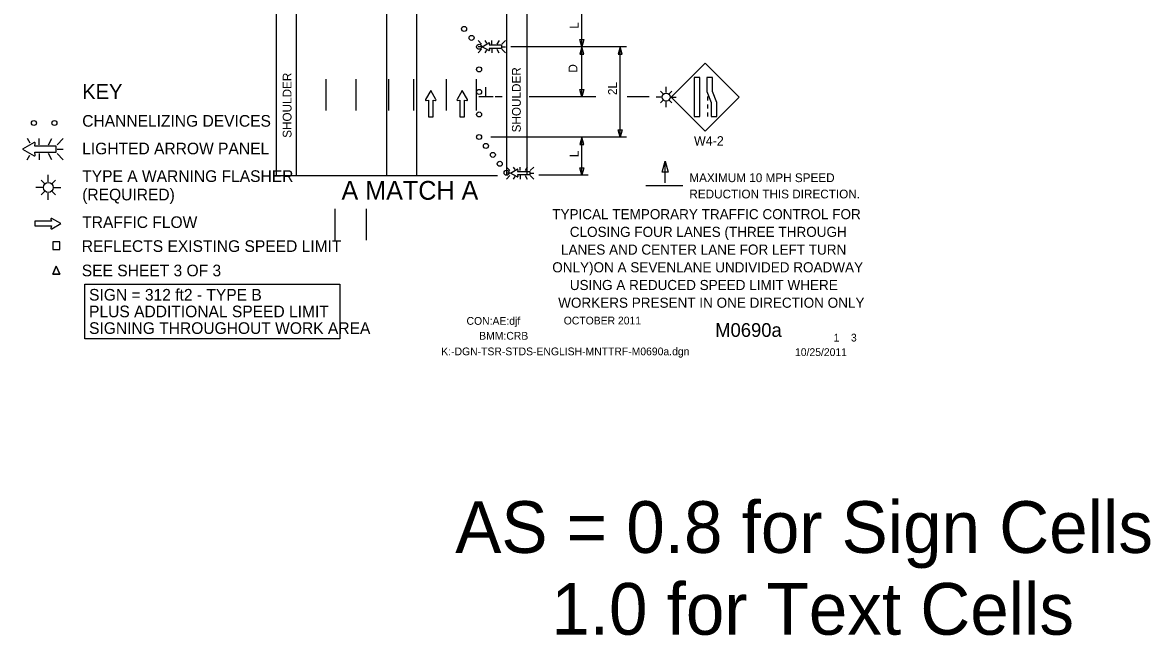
# Model space of a CAD drawing. Extents: x 16038 to 19504, y 5710 to 8321.
# Drawn here: x 16736 to 17637, y 5710 to 6199 of the extents above; entities that cross this region are included whole.
import ezdxf

# ---------------------------------------------------------------- set-up
doc = ezdxf.new("R2010")
doc.units = 0
for name, color, linetype in [('ALI_LEGAL_EX', 7, 'Continuous'), ('BORDER', 7, 'Continuous'), ('BORDER_SIGNAL_WO', 7, 'Continuous'), ('Level 3', 7, 'Continuous'), ('MT_SCRATCH_LEVEL_E', 7, 'Continuous'), ('PAVT_EDGE_EX', 7, 'Continuous'), ('TRAFFIC_SIGNS_PR', 7, 'Continuous'), ('TYPICAL_EX', 7, 'Continuous'), ('TYPICAL_TEXT_DIMEN_EX', 7, 'Continuous'), ('TYPICAL_TEXT_DIMEN_PR', 7, 'Continuous')]:
    doc.layers.add(name, color=color, linetype=linetype)

msp = doc.modelspace()

# ---------------------------------------------------------------- linework, layer by layer
at = {"layer": 'ALI_LEGAL_EX'}
for points in [[(16978.71, 6129.12), (16978.71, 6154.12)], [(17002.71, 6129.12), (17002.71, 6154.12)], [(17028.71, 6129.12), (17028.71, 6154.12)], [(17048.71, 6129.12), (17048.71, 6154.12)], [(17074.71, 6129.12), (17074.71, 6154.12)], [(17098.71, 6129.12), (17098.71, 6154.12)]]:
    msp.add_lwpolyline(points, dxfattribs=at)
at = {"layer": 'Level 3'}
for p, q in [((17119.19, 6139.95), (17113.47, 6139.95)), ((17193.93, 6139.95), (17140.74, 6139.95)), ((17236.44, 6139.95), (17218.89, 6139.95))]:
    msp.add_line(p, q, dxfattribs=at)
at = {"layer": 'MT_SCRATCH_LEVEL_E'}
for p, q in [((17062.15, 6145.03), (17058.03, 6137.79)), ((17062.15, 6145.03), (17058.03, 6137.79)), ((17066.29, 6137.79), (17062.15, 6145.03)), ((17066.29, 6137.79), (17062.15, 6145.03)), ((17087.24, 6145.03), (17083.12, 6137.79)), ((17087.24, 6145.03), (17083.12, 6137.79)), ((17091.38, 6137.79), (17087.24, 6145.03)), ((17091.38, 6137.79), (17087.24, 6145.03)), ((17058.52, 6137.11), (17060.29, 6137.42)), ((17058.52, 6137.11), (17060.29, 6137.42)), ((17060.29, 6137.42), (17060.29, 6124.16)), ((17060.29, 6137.42), (17060.29, 6124.16)), ((17064.04, 6124.16), (17064.04, 6137.42)), ((17064.04, 6137.42), (17065.81, 6137.11)), ((17064.04, 6124.16), (17064.04, 6137.42)), ((17064.04, 6137.42), (17065.81, 6137.11)), ((17083.61, 6137.11), (17085.38, 6137.42)), ((17083.61, 6137.11), (17085.38, 6137.42)), ((17085.38, 6137.42), (17085.38, 6124.16)), ((17085.38, 6137.42), (17085.38, 6124.16)), ((17089.13, 6124.16), (17089.13, 6137.42)), ((17089.13, 6137.42), (17090.9, 6137.11)), ((17089.13, 6124.16), (17089.13, 6137.42)), ((17089.13, 6137.42), (17090.9, 6137.11)), ((17060.29, 6124.16), (17064.04, 6124.16)), ((17060.29, 6124.16), (17064.04, 6124.16)), ((17085.38, 6124.16), (17089.13, 6124.16)), ((17085.38, 6124.16), (17089.13, 6124.16)), ((16758.92, 6042.47), (16759.24, 6040.69)), ((16758.92, 6042.47), (16759.24, 6040.69)), ((16766.85, 6038.84), (16759.61, 6042.95)), ((16766.85, 6038.84), (16759.61, 6042.95)), ((16759.24, 6040.69), (16745.98, 6040.69)), ((16745.98, 6040.69), (16745.98, 6036.95)), ((16759.24, 6040.69), (16745.98, 6040.69)), ((16745.98, 6040.69), (16745.98, 6036.95)), ((16745.98, 6036.95), (16759.24, 6036.95)), ((16745.98, 6036.95), (16759.24, 6036.95)), ((16759.24, 6036.95), (16758.92, 6035.17)), ((16759.24, 6036.95), (16758.92, 6035.17)), ((16759.61, 6034.69), (16766.85, 6038.84)), ((16759.61, 6034.69), (16766.85, 6038.84))]:
    msp.add_line(p, q, dxfattribs=at)
for centre, start, end in [((17058.44, 6137.56), 150.42484, 279.96381), ((17058.44, 6137.56), 150.42484, 279.96381), ((17065.88, 6137.57), 260.03619, 29.77312), ((17065.88, 6137.57), 260.03619, 29.77312), ((17083.53, 6137.56), 150.42484, 279.96381), ((17083.53, 6137.56), 150.42484, 279.96381), ((17090.97, 6137.57), 260.03619, 29.77312), ((17090.97, 6137.57), 260.03619, 29.77312), ((16759.38, 6042.54), 60.42484, 189.96381), ((16759.38, 6042.54), 60.42484, 189.96381), ((16759.38, 6035.1), 170.03619, 299.77312), ((16759.38, 6035.1), 170.03619, 299.77312)]:
    msp.add_arc(centre, 0.463, start, end, dxfattribs=at)
at = {"layer": 'PAVT_EDGE_EX'}
for p, q in [((16954.71, 6925.32), (16954.71, 6077.44)), ((17122.71, 6925.32), (17122.71, 6077.44)), ((17138.71, 6925.32), (17138.71, 6077.44)), ((16938.71, 6780.67), (16938.71, 6077.44)), ((17026.71, 6300.81), (17026.71, 6077.44)), ((17050.71, 6273.49), (17050.71, 6077.44))]:
    msp.add_line(p, q, dxfattribs=at)
for points in [[(16985.78, 6025.74), (16985.78, 6050.74)], [(16985.78, 6025.74), (16985.78, 6050.74)], [(17010.78, 6025.74), (17010.78, 6050.74)], [(17010.78, 6025.74), (17010.78, 6050.74)]]:
    msp.add_lwpolyline(points, dxfattribs=at)
at = {"layer": 'TRAFFIC_SIGNS_PR'}
for p, q in [((17099.94, 6184.87), (17102.76, 6182.05)), ((17102.76, 6180.02), (17099.94, 6180.02)), ((17099.94, 6175.17), (17102.76, 6177.99)), ((17105.38, 6184.87), (17106.59, 6182.78)), ((17106.67, 6177.36), (17105.4, 6175.17)), ((17110.85, 6182.05), (17110.85, 6184.87)), ((17110.85, 6177.99), (17110.85, 6175.17)), ((17114.98, 6177.99), (17116.61, 6175.17)), ((17116.64, 6184.87), (17115.01, 6182.05)), ((17118.93, 6182.05), (17121.76, 6184.88)), ((17118.93, 6180.02), (17121.76, 6180.02)), ((17118.93, 6177.99), (17121.76, 6175.17)), ((17281.32, 6166.91), (17254.17, 6139.76)), ((17308.48, 6139.76), (17281.32, 6166.91)), ((17247.57, 6142.36), (17245.46, 6144.46)), ((17250.08, 6143.4), (17250.08, 6147.9)), ((17252.59, 6142.36), (17254.7, 6144.46)), ((17246.93, 6139.84), (17242.09, 6139.84)), ((17247.57, 6137.33), (17245.46, 6135.22)), ((17250.08, 6131.88), (17250.08, 6136.29)), ((17252.59, 6137.33), (17254.7, 6135.22)), ((17253.23, 6139.84), (17258.12, 6139.84)), ((17254.17, 6139.76), (17281.32, 6112.6)), ((17281.32, 6112.6), (17308.48, 6139.76)), ((17282.97, 6140.25), (17282.97, 6137.05)), ((17282.97, 6133.85), (17282.97, 6130.65)), ((17282.97, 6127.45), (17282.97, 6124.25)), ((16742.29, 6102.95), (16740.09, 6106.78)), ((16749.61, 6101.84), (16749.61, 6106.78)), ((16756.85, 6101.84), (16759.7, 6106.78)), ((16763.76, 6101.84), (16768.7, 6106.78)), ((16763.76, 6098.29), (16768.7, 6098.29)), ((16740.04, 6089.79), (16742.15, 6093.46)), ((16749.61, 6094.73), (16749.61, 6089.79)), ((16759.74, 6089.79), (16756.89, 6094.73)), ((16763.76, 6094.73), (16768.7, 6089.79)), ((17122.54, 6083.98), (17125.36, 6081.16)), ((17125.36, 6079.13), (17122.54, 6079.13)), ((17127.98, 6083.98), (17129.18, 6081.89)), ((17133.44, 6081.16), (17133.44, 6083.98)), ((17139.23, 6083.98), (17137.6, 6081.16)), ((17141.53, 6081.16), (17144.35, 6083.98)), ((17141.53, 6079.13), (17144.35, 6079.13)), ((16753.68, 6070.82), (16751.05, 6073.45)), ((16753.68, 6070.82), (16751.05, 6073.45)), ((16756.82, 6072.12), (16756.82, 6077.74)), ((16756.82, 6072.12), (16756.82, 6077.74)), ((16759.95, 6070.82), (16762.59, 6073.45)), ((16759.95, 6070.82), (16762.59, 6073.45)), ((17122.54, 6074.28), (17125.36, 6077.1)), ((17129.26, 6076.46), (17128, 6074.28)), ((17133.44, 6077.1), (17133.44, 6074.28)), ((17137.58, 6077.1), (17139.21, 6074.28)), ((17141.53, 6077.1), (17144.35, 6074.28)), ((16752.88, 6067.68), (16746.84, 6067.68)), ((16752.88, 6067.68), (16746.84, 6067.68)), ((16753.68, 6064.55), (16751.05, 6061.92)), ((16753.68, 6064.55), (16751.05, 6061.92)), ((16756.82, 6057.74), (16756.82, 6063.25)), ((16756.82, 6057.74), (16756.82, 6063.25)), ((16759.95, 6064.55), (16762.58, 6061.92)), ((16759.95, 6064.55), (16762.58, 6061.92)), ((16760.75, 6067.68), (16766.85, 6067.68)), ((16760.75, 6067.68), (16766.85, 6067.68))]:
    msp.add_line(p, q, dxfattribs=at)
for points in [[(17108.52, 6177.01), (17103.21, 6180.02), (17108.52, 6183.06)], [(17109.02, 6182.7), (17108.79, 6181.41), (17118.51, 6181.41), (17118.51, 6178.66), (17108.79, 6178.66), (17109.02, 6177.36)], [(16745.54, 6103.56), (16736.25, 6098.29), (16745.54, 6092.96)], [(16746.42, 6093.59), (16746.01, 6095.86), (16763.03, 6095.86), (16763.03, 6100.66), (16746.01, 6100.66), (16746.42, 6102.94)], [(17131.12, 6076.11), (17125.81, 6079.13), (17131.12, 6082.17)], [(17131.62, 6081.81), (17131.39, 6080.51), (17141.11, 6080.51), (17141.11, 6077.77), (17131.39, 6077.77), (17131.62, 6076.47)], [(16763.11, 6004.77), (16760.31, 5998.6)], [(16760.31, 5998.6), (16763.11, 6004.77)], [(16760.31, 5998.6), (16765.9, 5998.6)], [(16765.9, 5998.6), (16760.31, 5998.6)], [(16765.9, 5998.6), (16763.11, 6004.77)], [(16763.11, 6004.77), (16765.9, 5998.6)]]:
    msp.add_lwpolyline(points, dxfattribs=at)
for points in [[(17272.43, 6155.49), (17272.43, 6124.25), (17276.92, 6124.25), (17276.92, 6155.49)], [(17282.57, 6155.49), (17282.57, 6144.31), (17285.91, 6135.43), (17285.91, 6124.25), (17290.4, 6124.25), (17290.4, 6135.43), (17287.06, 6144.31), (17287.06, 6155.49)], [(16760.31, 6018.05), (16765.9, 6018.05), (16765.9, 6024.23), (16760.31, 6024.23)]]:
    msp.add_lwpolyline(points, close=True, dxfattribs=at)
for centre, radius in [((17088.71, 6194.23), 2), ((17094.71, 6187.09), 2), ((17100.71, 6179.95), 2), ((17100.71, 6161.95), 2), ((17100.71, 6143.95), 2), ((17250.08, 6139.84), 3.15), ((17100.71, 6125.95), 2), ((16745.34, 6119.13), 2), ((16761.64, 6119.13), 2), ((17100.71, 6107.95), 2), ((17106.21, 6100.82), 2), ((17111.7, 6093.69), 2), ((17117.2, 6086.56), 2), ((17122.7, 6079.44), 2), ((16756.82, 6067.68), 3.94), ((16756.82, 6067.68), 3.94)]:
    msp.add_circle(centre, radius, dxfattribs=at)
for centre, radius, start, end in [((17108.69, 6182.76), 0.341, 350.04067, 118.51671), ((17108.69, 6177.31), 0.341, 241.10835, 9.26922), ((16745.83, 6103.04), 0.598, 350.73078, 118.89165), ((16745.83, 6093.49), 0.597, 241.48329, 9.95933), ((17131.28, 6081.87), 0.341, 350.04067, 118.51671), ((17131.28, 6076.41), 0.341, 241.10835, 9.26922)]:
    msp.add_arc(centre, radius, start, end, dxfattribs=at)
at = {"layer": 'TYPICAL_EX'}
msp.add_line((16938.71, 6925.32), (16938.71, 6077.44), dxfattribs=at)
at = {"layer": 'TYPICAL_TEXT_DIMEN_EX'}
msp.add_lwpolyline([(16786.01, 5990.47), (16989.65, 5990.47), (16989.65, 5946.9), (16786.01, 5946.9)], close=True, dxfattribs=at)
at = {"layer": 'TYPICAL_TEXT_DIMEN_PR'}
for p, q in [((17182.71, 6179.95), (17182.71, 6210.46)), ((17187.71, 6179.95), (17126.02, 6179.95)), ((17218.29, 6179.95), (17128.01, 6179.95)), ((17182.71, 6179.95), (17181.14, 6185.81)), ((17181.14, 6185.81), (17182.71, 6185.81)), ((17182.71, 6179.95), (17181.14, 6174.09)), ((17182.71, 6185.81), (17184.28, 6185.81)), ((17184.28, 6185.81), (17182.71, 6179.95)), ((17182.71, 6139.95), (17182.71, 6179.95)), ((17184.28, 6174.09), (17182.71, 6179.95)), ((17213.29, 6179.95), (17211.72, 6174.09)), ((17213.29, 6107.95), (17213.29, 6179.95)), ((17214.86, 6174.09), (17213.29, 6179.95)), ((17181.14, 6174.09), (17182.71, 6174.09)), ((17182.71, 6174.09), (17184.28, 6174.09)), ((17211.72, 6174.09), (17213.29, 6174.09)), ((17213.29, 6174.09), (17214.86, 6174.09)), ((17106.22, 6140.07), (17106.22, 6147.86)), ((17182.71, 6139.95), (17181.14, 6145.81)), ((17181.14, 6145.81), (17182.71, 6145.81)), ((17182.71, 6145.81), (17184.28, 6145.81)), ((17184.28, 6145.81), (17182.71, 6139.95)), ((17111.84, 6140.07), (17100.59, 6140.07)), ((17218.29, 6107.95), (17110.17, 6107.95)), ((17182.71, 6107.95), (17181.14, 6102.09)), ((17182.71, 6077.44), (17182.71, 6107.95)), ((17184.28, 6102.09), (17182.71, 6107.95)), ((17213.29, 6107.95), (17211.72, 6113.81)), ((17211.72, 6113.81), (17213.29, 6113.81)), ((17213.29, 6113.81), (17214.86, 6113.81)), ((17214.86, 6113.81), (17213.29, 6107.95)), ((17181.14, 6102.09), (17182.71, 6102.09)), ((17182.71, 6102.09), (17184.28, 6102.09)), ((17246.86, 6079.77), (17249.22, 6088.56)), ((17249.22, 6071.44), (17249.22, 6088.56)), ((17249.22, 6088.56), (17251.57, 6079.77)), ((17182.71, 6077.44), (17181.14, 6083.3)), ((17181.14, 6083.3), (17182.71, 6083.3)), ((17182.71, 6083.3), (17184.28, 6083.3)), ((17184.28, 6083.3), (17182.71, 6077.44)), ((17249.22, 6079.77), (17246.86, 6079.77)), ((17251.57, 6079.77), (17249.22, 6079.77)), ((16936.37, 6077.28), (17115.53, 6077.28)), ((17187.71, 6077.44), (17148.38, 6077.44)), ((17263.39, 6068.94), (17233.95, 6068.94))]:
    msp.add_line(p, q, dxfattribs=at)

# ---------------------------------------------------------------- texts
at = {"layer": 'BORDER'}
for s, p in [('TYPICAL TEMPORARY TRAFFIC CONTROL FOR ', (17159.13, 6042.33)), ('CLOSING FOUR LANES (THREE THROUGH ', (17173.13, 6028.2)), ('LANES AND CENTER LANE FOR LEFT TURN ', (17166.13, 6014.06)), ('ONLY)ON A SEVENLANE UNDIVIDED ROADWAY ', (17159.13, 5999.92)), ('USING A REDUCED SPEED LIMIT WHERE ', (17173.13, 5985.79)), ('WORKERS PRESENT IN ONE DIRECTION ONLY', (17163.87, 5971.65))]:
    msp.add_text(s, height=8.066, dxfattribs=at).set_placement(p)
at = {"layer": 'BORDER_SIGNAL_WO'}
for s, height, p in [('CON:AE:djf', 6.2, (17090.69, 5958.06)), ('    OCTOBER 2011    ', 6.2, (17159.08, 5958.34)), ('BMM:CRB   ', 6.2, (17100.81, 5946.17)), ('    M0690a   ', 11, (17272.86, 5948.38)), (' 1    3 ', 6.2, (17381.45, 5944.7)), ('K:-DGN-TSR-STDS-ENGLISH-MNTTRF-M0690a.dgn        ', 6.2, (17070.55, 5933.71)), ('10/25/2011    ', 6.2, (17352.93, 5933.13)), ('AS = 0.8 for Sign Cells', 41.2877, (17081.69, 5775.96)), ('     1.0 for Text Cells', 41.2877, (17081.69, 5710.67))]:
    msp.add_text(s, height=height, dxfattribs=at).set_placement(p)
at = {"layer": 'TRAFFIC_SIGNS_PR'}
msp.add_text('W4-2', height=7.44, dxfattribs=at).set_placement((17272.28, 6101.16))
at = {"layer": 'TYPICAL_TEXT_DIMEN_EX'}
for s, height, p in [('KEY', 12, (16783.88, 6138.23)), ('CHANNELIZING DEVICES', 9.3, (16783.88, 6116.18)), ('LIGHTED ARROW PANEL', 9.3, (16783.88, 6094.13)), ('TYPE A WARNING FLASHER', 9.3, (16783.88, 6072.08)), ('(REQUIRED)', 9.3, (16783.88, 6057.38)), ('TRAFFIC FLOW', 9.3, (16783.88, 6035.33)), ('REFLECTS EXISTING SPEED LIMIT', 9.3, (16783.52, 6016.22)), ('SEE SHEET 3 OF 3', 9.3, (16783.52, 5996.76)), ('SIGN = 312 ft2 - TYPE B', 9.3, (16789.35, 5977.36)), ('PLUS ADDITIONAL SPEED LIMIT', 9.3, (16789.35, 5964.06)), ('SIGNING THROUGHOUT WORK AREA', 9.3, (16789.35, 5950.76))]:
    msp.add_text(s, height=height, dxfattribs=at).set_placement(p)
at = {"layer": 'TYPICAL_TEXT_DIMEN_PR'}
for s, p in [('L', (17180.15, 6194.35)), ('SHOULDER', (17133.99, 6111.64)), ('D', (17179.14, 6159.36)), ('SHOULDER', (16950.95, 6107.3)), ('2L', (17210.73, 6141.44)), ('L', (17180.15, 6091.84))]:
    msp.add_text(s, height=7, rotation=90, dxfattribs=at).set_placement(p)
for s, height, p in [('MAXIMUM 10 MPH SPEED', 7, (17268.57, 6071.95)), ('A MATCH A', 15, (16990.88, 6057.87)), ('REDUCTION THIS DIRECTION.', 7, (17268.57, 6058.95))]:
    msp.add_text(s, height=height, dxfattribs=at).set_placement(p)

doc.saveas('drawing.dxf')
